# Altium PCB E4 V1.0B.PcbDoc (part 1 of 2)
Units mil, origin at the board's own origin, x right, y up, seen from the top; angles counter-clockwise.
Board outline 3543.31 x 2637.8 mil, 2 copper layers (Top Layer, Bottom Layer), stack 77.559 mil thick; 151 components, 120 nets, 552 pads, 470 vias.
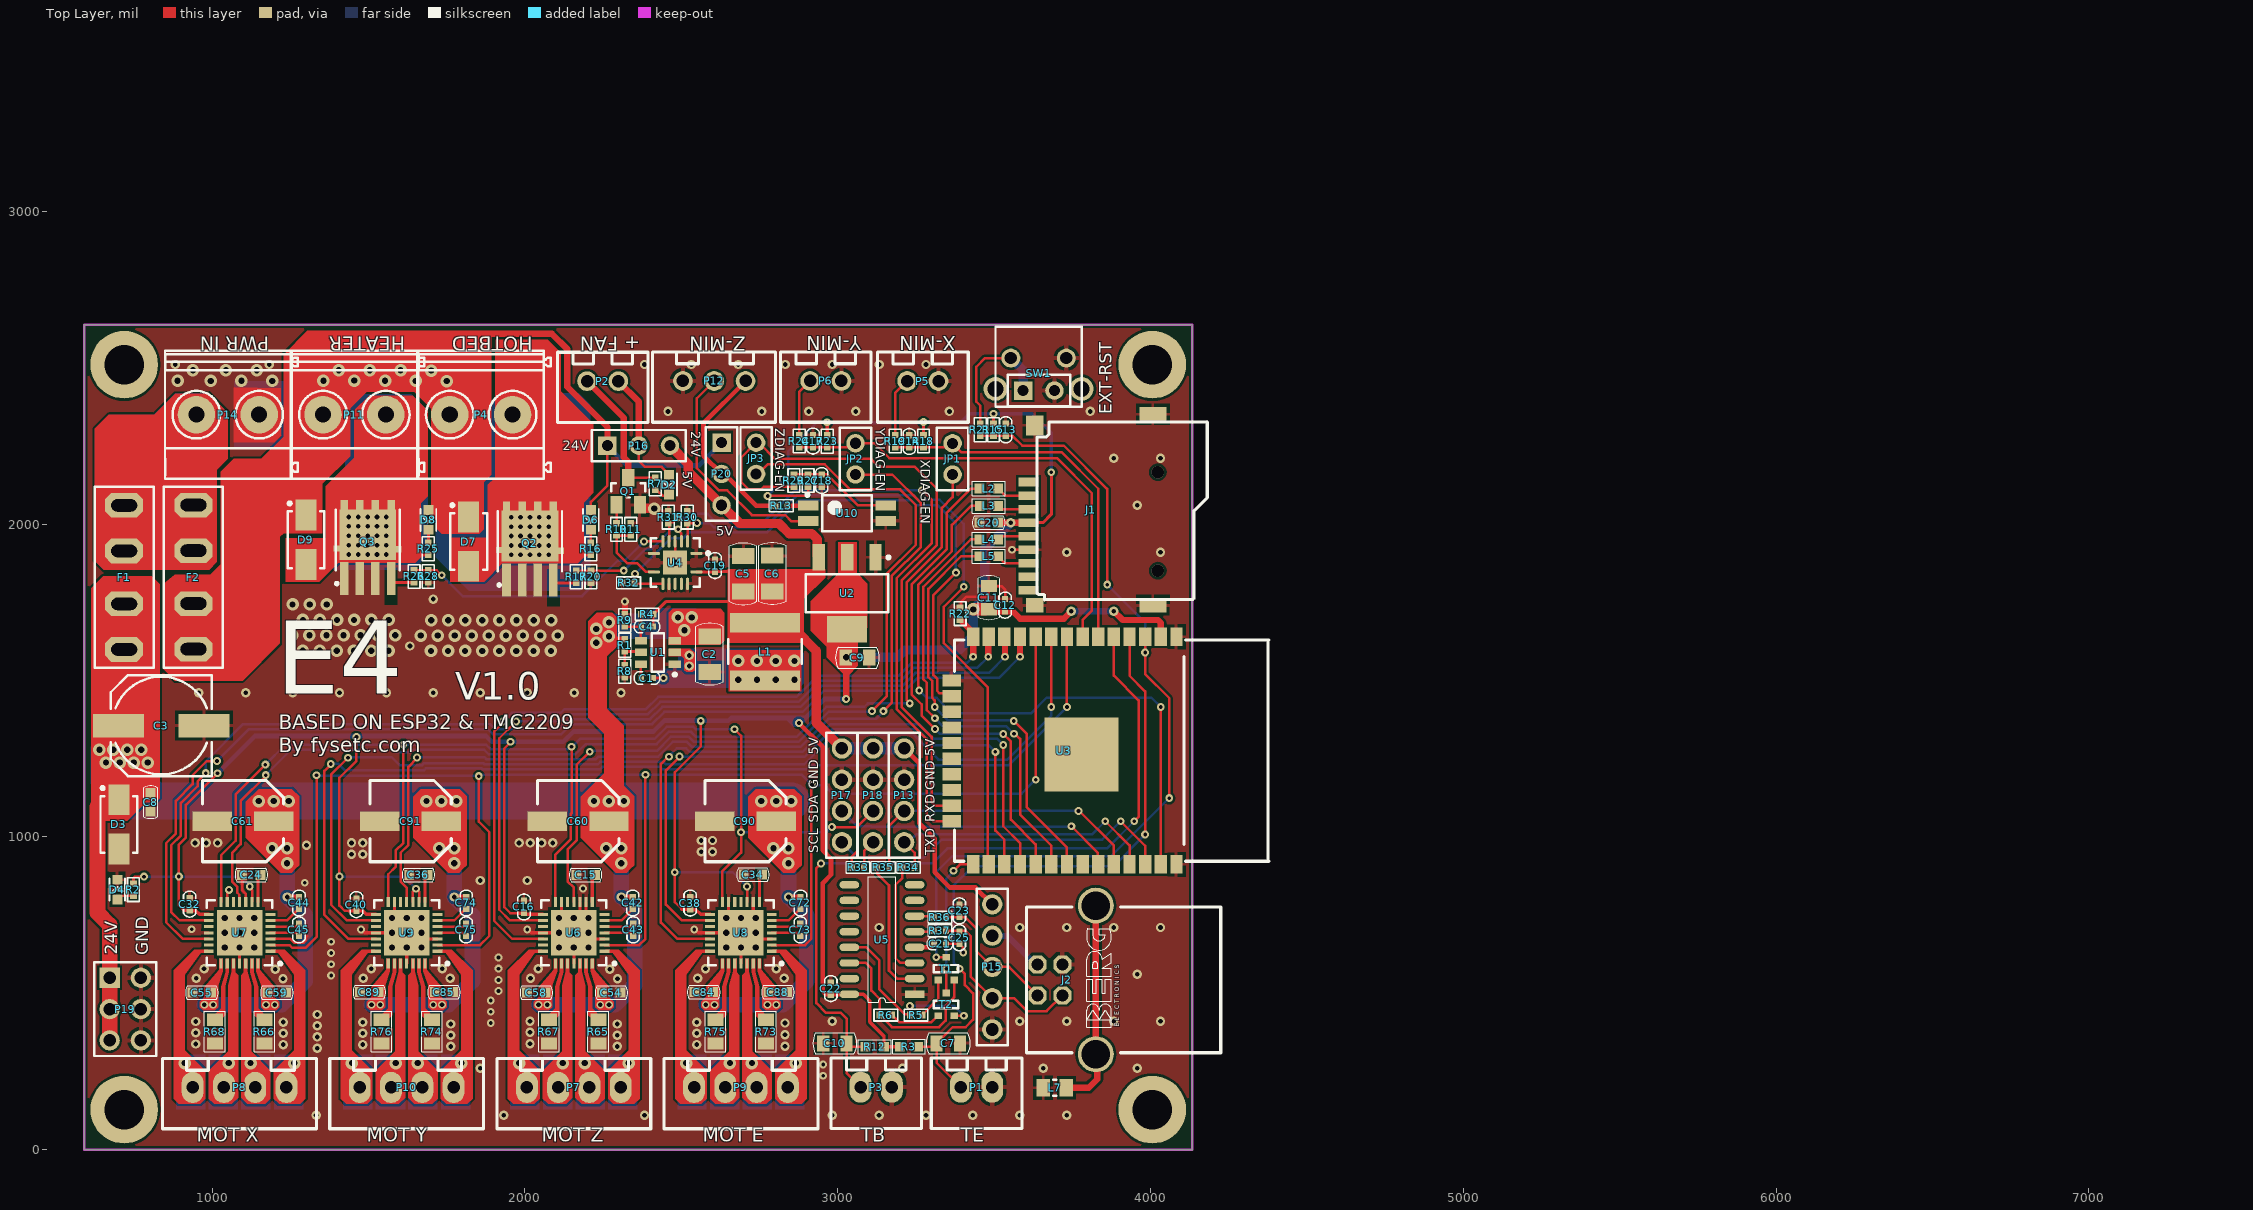
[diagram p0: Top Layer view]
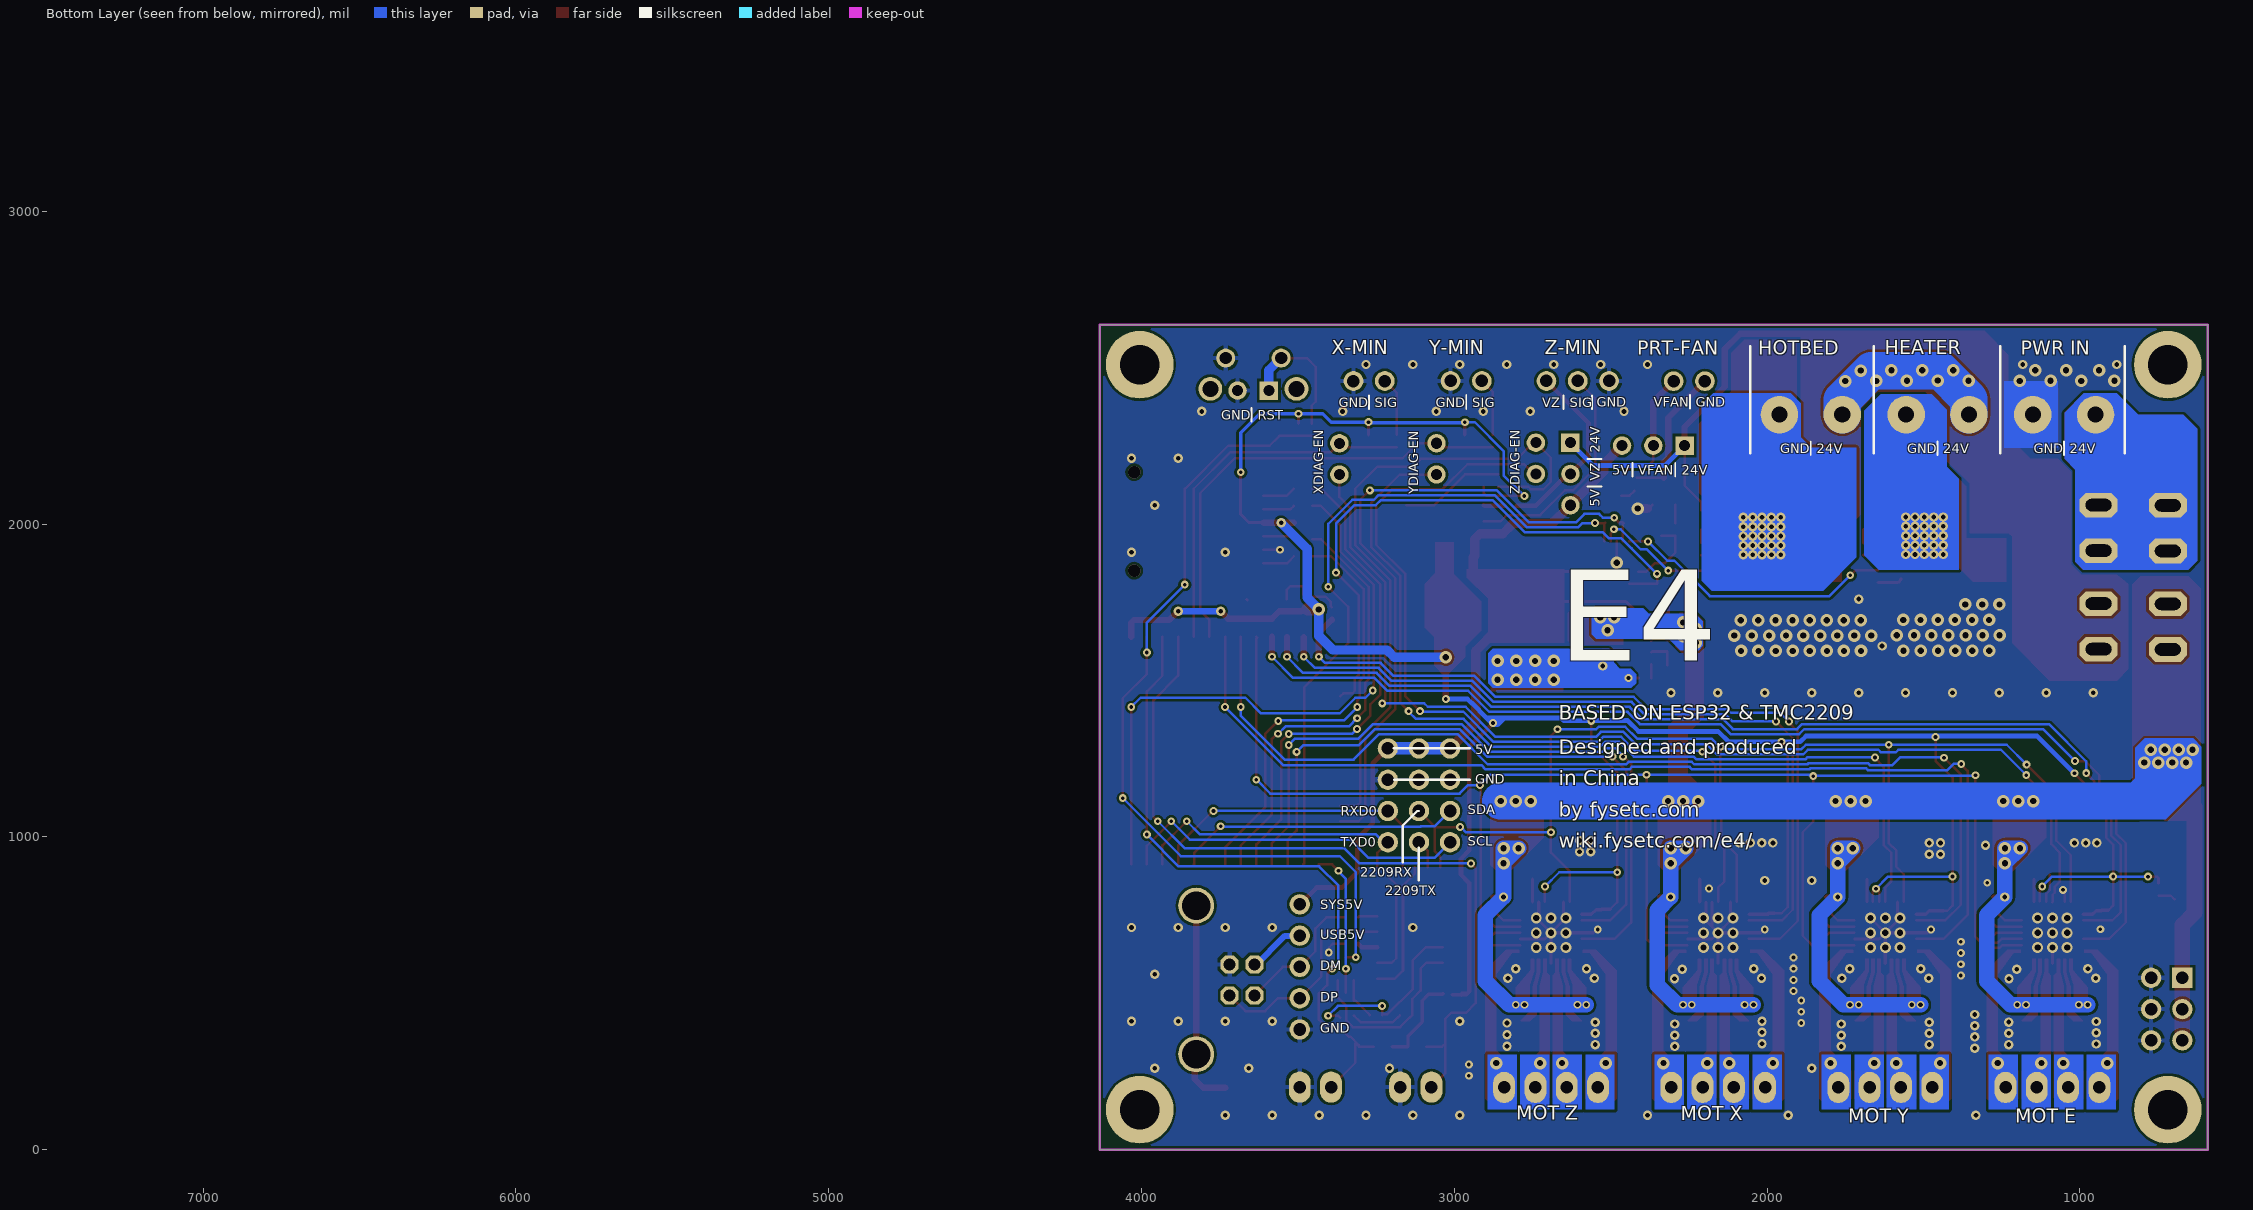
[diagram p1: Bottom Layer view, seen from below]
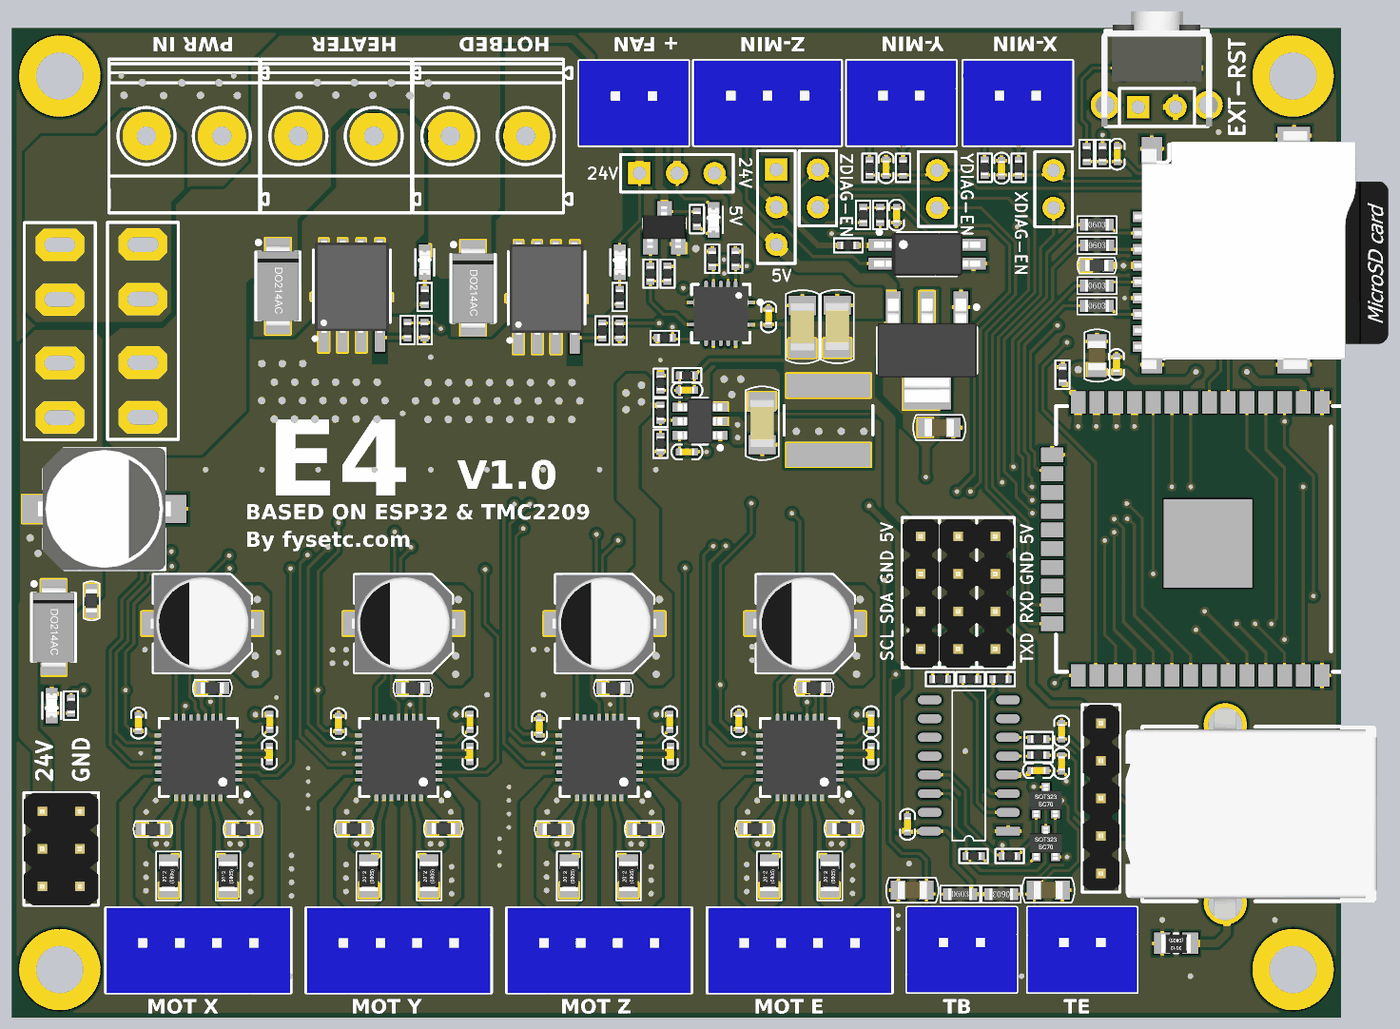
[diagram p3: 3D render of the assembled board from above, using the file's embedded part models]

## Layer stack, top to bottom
Top Solder: solder mask 0.4, Solder Resist, Dk 3.5
Top Layer: signal copper 1.378
Dielectric 1: core 7.874, FR-4, Dk 4.2
Dielectric 2: prepreg 59.0551, Dk 4.2
Dielectric 3: core 7.874, Dk 4.2
Bottom Layer: signal copper 1.378
Bottom Solder: solder mask 0.4, Solder Resist, Dk 3.5

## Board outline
590.55,0 590.55,2637.8 4133.86,2637.8 4133.86,0

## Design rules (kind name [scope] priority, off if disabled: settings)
Clearance Clearance_1 [(InDifferentialPairClass('All Differential Pairs'))] p1: gap=6 ignorepadtopadclearanceinfootprint=TRUE
Clearance [All] p2: gap=8 ignorepadtopadclearanceinfootprint=TRUE
DiffPairsRouting DiffPairsRouting_90R [InDifferentialPairClass('USB')] p1: maxlimit=6 minlimit=6 mostfreqgap=6 toplayer_minwidth=9 toplayer_maxwidth=9 toplayer_prefwidth=9 bottomlayer_minwidth=9 bottomlayer_maxwidth=9 bottomlayer_prefwidth=9 maxuncoupledlength=500
DiffPairsRouting DiffPairsRouting_100R [InDifferentialPairClass('ETH')] p2: maxlimit=6 minlimit=6 mostfreqgap=6 toplayer_minwidth=6.89 toplayer_maxwidth=6.89 toplayer_prefwidth=6.89 bottomlayer_minwidth=6.89 bottomlayer_maxwidth=6.89 bottomlayer_prefwidth=6.89 maxuncoupledlength=500
PolygonConnect PolygonConnect_8 [All vs (HasFootprint('MCCQ-122') or HasFootprint('黄铜镀锡4.8mm插片'))] p1: connectstyle=Direct reliefconductorwidth=10 reliefentries=4 polygonreliefangle="90 Angle" airgapwidth=10
PolygonConnect PolygonConnect_7 [All vs HasFootprint('KPJX-4S')] p2: connectstyle=Direct reliefconductorwidth=10 reliefentries=4 polygonreliefangle="90 Angle" airgapwidth=10
PolygonConnect PolygonConnect_6 [All vs HasFootprint('AO_DFN5x6')] p3: thpad.connectstyle=Relief thpad.reliefconductorwidth=10 thpad.reliefentries=4 thpad.polygonreliefangle="90 Angle" thpad.airgapwidth=10 smdpad.connectstyle=Direct smdpad.reliefconductorwidth=10 smdpad.reliefentries=4 smdpad.polygonreliefangle="90 Angle" smdpad.airgapwidth=10 via.connectstyle=Direct via.reliefconductorwidth=10 via.reliefentries=4 via.polygonreliefangle="90 Angle" via.airgapwidth=10
PolygonConnect PolygonConnect_5 [All vs HasFootprint('CAP0603')] p4: thpad.connectstyle=Relief thpad.reliefconductorwidth=10 thpad.reliefentries=4 thpad.polygonreliefangle="90 Angle" thpad.airgapwidth=10 smdpad.connectstyle=Direct smdpad.reliefconductorwidth=10 smdpad.reliefentries=4 smdpad.polygonreliefangle="90 Angle" smdpad.airgapwidth=10 via.connectstyle=Direct via.reliefconductorwidth=10 via.reliefentries=4 via.polygonreliefangle="90 Angle" via.airgapwidth=10
PolygonConnect PolygonConnect_4 [All vs HasFootprint('8*10.5')] p5: thpad.connectstyle=Relief thpad.reliefconductorwidth=10 thpad.reliefentries=4 thpad.polygonreliefangle="90 Angle" thpad.airgapwidth=10 smdpad.connectstyle=Direct smdpad.reliefconductorwidth=10 smdpad.reliefentries=4 smdpad.polygonreliefangle="90 Angle" smdpad.airgapwidth=10 via.connectstyle=Direct via.reliefconductorwidth=10 via.reliefentries=4 via.polygonreliefangle="90 Angle" via.airgapwidth=10
PolygonConnect PolygonConnect_3 [All vs HasFootprint('DO214AC (SMA)')] p6: thpad.connectstyle=Relief thpad.reliefconductorwidth=10 thpad.reliefentries=4 thpad.polygonreliefangle="90 Angle" thpad.airgapwidth=10 smdpad.connectstyle=Direct smdpad.reliefconductorwidth=10 smdpad.reliefentries=4 smdpad.polygonreliefangle="90 Angle" smdpad.airgapwidth=10 via.connectstyle=Direct via.reliefconductorwidth=10 via.reliefentries=4 via.polygonreliefangle="90 Angle" via.airgapwidth=10
PolygonConnect PolygonConnect_2 [All vs HasFootprint('RES0805')] p7: thpad.connectstyle=Relief thpad.reliefconductorwidth=10 thpad.reliefentries=4 thpad.polygonreliefangle="90 Angle" thpad.airgapwidth=10 smdpad.connectstyle=Direct smdpad.reliefconductorwidth=10 smdpad.reliefentries=4 smdpad.polygonreliefangle="90 Angle" smdpad.airgapwidth=10 via.connectstyle=Direct via.reliefconductorwidth=10 via.reliefentries=4 via.polygonreliefangle="90 Angle" via.airgapwidth=10
PolygonConnect [All vs HasFootprint('ELCO Case D')] p8: thpad.connectstyle=Relief thpad.reliefconductorwidth=10 thpad.reliefentries=4 thpad.polygonreliefangle="90 Angle" thpad.airgapwidth=10 smdpad.connectstyle=Direct smdpad.reliefconductorwidth=10 smdpad.reliefentries=4 smdpad.polygonreliefangle="90 Angle" smdpad.airgapwidth=10 via.connectstyle=Direct via.reliefconductorwidth=10 via.reliefentries=4 via.polygonreliefangle="90 Angle" via.airgapwidth=10
PolygonConnect PolygonConnect_1 [All] p9: thpad.connectstyle=Relief thpad.reliefconductorwidth=15 thpad.reliefentries=4 thpad.polygonreliefangle="90 Angle" thpad.airgapwidth=10 smdpad.connectstyle=Relief smdpad.reliefconductorwidth=10 smdpad.reliefentries=4 smdpad.polygonreliefangle="90 Angle" smdpad.airgapwidth=10 via.connectstyle=Direct via.reliefconductorwidth=10 via.reliefentries=4 via.polygonreliefangle="90 Angle" via.airgapwidth=10
RoutingVias [All] p1: holewidth=28 width=50 viastyle="Through Hole" minholewidth=12 minwidth=25 maxholewidth=28 maxwidth=50
SolderMaskExpansion [All] p1: expansion=4 istentingtop=FALSE
Width [All] p1: maxlimit=999 minlimit=6 preferedwidth=8
29 further rules are at their usual default settings.

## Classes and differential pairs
component class "U_Trinamic driver": C15 C16 C24 C32 C34 C36 C38 C40 C42 C43 C44 C45 C54 C55 C58 C59 C60 C61 C72 C73 C74 C75 C84 C85 C88 C89 C90 C91 P7 P8 P9 P10 R65 R66 R67 R68 R73 R74 R75 R76 U6 U7 U8 U9
component class E4_V1.0: C1 C2 C3 C4 C5 C6 C7 C8 C9 C10 C11 C12 C13 C14 C17 C18 C19 C20 C21 C22 C23 C25 D2 D3 D4 D6 D7 D8 D9 EXT-RST F1 F2 J1 J2 JP1 JP2 JP3 L1 L2 L3 L4 L5 L7 P1 P2 P3 P4 P5 P6 P11 P12 P13 P14 P15 P16 P17 P18 P19 P20 Q1 Q2 Q3 R1 R2 R3 R4 R5 R6 R7 R8 R9 R10 R11 R12 R13 R15 R16 R17 R18 R19 R20 R21 R22 R23 R24 R25 R26 R27 R28 R29 R30 R31 R32 R33 R34 R35 R36 R37 SW1 T1 T2 U1 U2 U3 U4 U5 U10

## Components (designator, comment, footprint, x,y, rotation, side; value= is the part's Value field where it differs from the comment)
C1 "0.1uF" CAP0402 2390.26,1507.99 r0 top value=100nF
C2 "10uF/35V" CAP1206 2590.7,1584.26 r90 top
C3 "330uF/35V" CASE_E7 837,1356 r90 top
C4 "100pF" CAP0402 2390.26,1672.27 r180 top value=47pF
C5 "100uF/10V" CAP1206 2697.93,1841.13 r90 top value=47uF
C6 "100uF/10V" CAP1206 2790.93,1842.13 r90 top value=47uF
C7 "10uF" CAP0805 3353.45,339.73 r180 top
C8 "100nF" CAP0603 803,1111 r90 top
C9 "10uF" CAP0805 3063,1572.87 r180 top
C10 "10uF" CAP0805 2990.88,339.73 r0 top
C11 "10uF" CAP0805 3483,1764.77 r90 top
C12 "100nF" CAP0402 3535.19,1740.86 r270 top
C13 "100nF" CAP0402 3537.11,2301.7 r90 top
C14 "100nF" CAP0402 3228.84,2264.33 r90 top
C15 "4.7uF" CAP0603 2193.94,878.59 r180 top value=100nF
C16 "100nF" CAP0402 1996.74,775.94 r270 top
C17 "100nF" CAP0402 2920.81,2265.59 r90 top
C18 "100nF" CAP0402 2948.92,2139.33 r270 top
C19 "100nF" CAP0402 2607.84,1867.65 r270 top
C20 "10uF" CAP0603 3483,2005.11 r180 top
C21 "100nF" CAP0402 3327,658.21 r180 top
C22 "100nF" CAP0402 2978,515.03 r270 top
C23 "47pF" CAP0402 3389,763.43 r270 top
C24 "4.7uF" CAP0603 1125.14,878.59 r180 top value=100nF
C25 "47pF" CAP0402 3389,677.6 r90 top
C32 "100nF" CAP0402 928.08,785.1 r270 top
C34 "4.7uF" CAP0603 2728.98,879.59 r180 top value=100nF
C36 "4.7uF" CAP0603 1659.47,878.59 r180 top value=100nF
C38 "100nF" CAP0402 2528.34,788.57 r270 top
C40 "100nF" CAP0402 1461.07,783.57 r270 top
C42 "100nF" CAP0402 2344.5,788.65 r270 top
C43 "22nF" CAP0402 2346.06,702.94 r270 top value=100nF
C44 "100nF" CAP0402 1277.83,788.65 r270 top
C45 "22nF" CAP0402 1277.4,702.94 r270 top value=100nF
C54 "100nF" CAP0603 2276.4,502.28 r180 top
C55 "100nF" CAP0603 966.88,502.29 r0 top
C58 "100nF" CAP0603 2036.41,502.28 r0 top
C59 "100nF" CAP0603 1206.81,502.29 r180 top
C60 "100uF/35V" "ELCO Case D" 2170.27,1050.26 r0 top
C61 "100uF/35V" "ELCO Case D" 1098.41,1050.26 r0 top
C72 "100nF" CAP0402 2880.83,788.65 r270 top
C73 "22nF" CAP0402 2880.4,702.94 r270 top value=100nF
C74 "100nF" CAP0402 1812.17,788.65 r270 top
C75 "22nF" CAP0402 1811.73,702.94 r270 top value=100nF
C84 "100nF" CAP0603 2571.7,503.84 r0 top
C85 "100nF" CAP0603 1740.93,503.84 r180 top
C88 "100nF" CAP0603 2808.77,503.84 r180 top
C89 "100nF" CAP0603 1502.34,503.84 r0 top
C90 "100uF/35V" "ELCO Case D" 2705.19,1050.26 r0 top
C91 "100uF/35V" "ELCO Case D" 1634.5,1050.26 r0 top
D2 "LED_0603" LED0603 2460.76,2126.43 r180 top
D3 "SMAJ28A" "DO214AC (SMA)" 702,1040 r90 top
D4 "LED黄色" LED0603 696.8,831.44 r0 top
D6 "LED_0603" LED0603 2211.08,2013.37 r180 top
D7 "SK310A-TP" "DO214AC (SMA)" 1820.08,1944.28 r90 top
D8 "LED_0603" LED0603 1691.25,2013.37 r180 top
D9 "SK310A-TP" "DO214AC (SMA)" 1299.98,1950 r90 top
EXT-RST "Header 2" HDR1X2#1 3593,2427 r0 top
F1 "3A" MCCQ-122 718.5,1914.29 r180 top
F2 "7.5A" MCCQ-122 940,1915.29 r180 top
J1 "TFcard" MicroSD_1 4023.43,2166.06 r90 top
J2 "USB connector" CON-BERG_PN61729-S 3825.21,542.34 r90 top
JP1 "Jumper-2P-Open" HDR1X2#2 3367.4,2158.42 r90 top
JP2 "Jumper-2P-Open" HDR1X2#2 3056.86,2158.67 r90 top
JP3 "Jumper-2P-Open" HDR1X2#2 2739.26,2160.42 r90 top
L1 "22uH" NRS6045 2767.61,1592.25 r90 top
L2 "Bead" RES0603 3483,2113.69 r0 top
L3 "Bead" RES0603 3483.47,2058.51 r0 top
L4 "Bead" RES0603 3483,1951.11 r0 top
L5 "Bead" RES0603 3483,1897.37 r0 top
L7 "Bead" L0805 3694,198 r180 top
P1 "Header 2" XH2.54-2P-L#1 3444,200 r0 top
P2 "Header 2" XH2.54-2P-L#2 2248.68,2457 r0 top
P3 "Header 2" XH2.54-2P-L#1 3123,200 r0 top
P4 "Header 2" KF128/129 1860,2350 r0 top
P5 "Header 2" XH2.54-2P-L#2 3272.32,2457.57 r0 top
P6 "Header 2" XH2.54-2P-L#2 2961.86,2457.83 r0 top
P7 "Header 4" XH2.54-4P-L 2156.27,198.89 r0 top
P8 "Header 4" XH2.54-4P-L 1087.61,198.89 r0 top
P9 "Header 4" XH2.54-4P-L 2690.61,198.89 r0 top
P10 "Header 4" XH2.54-4P-L 1621.94,198.89 r0 top
P11 "Header 2" KF128/129 1454.84,2350 r0 top
P12 "Header 3" XH2.54-3P-L 2605.26,2457.65 r0 top
P13 "Header 4" "Header 1X4" 3212.38,982.85 r90 top
P14 "Header 2" KF128/129 1050,2350 r0 top
P15 "Header 5" "Header 1X5" 3494,784.26 r270 top
P16 "Header 3" HDR1X3 2263.68,2251 r0 top
P17 "Header 4" "Header 1X4" 3013.62,982.85 r90 top
P18 "Header 4" "Header 1X4" 3113,982.85 r90 top
P19 "Header 3X2" "Header 2X3" 672.02,549.44 r270 top
P20 "Header 3" HDR1X3 2628.7,2260.42 r270 top
Q1 "MMBF170" SOT23-3 2330.22,2105.16 r180 top
Q2 "WSD40150" AO_DFN5x6 2016.09,1943.08 r0 top value=IRF8736PBF
Q3 "WSD4060" AO_DFN5x6 1496.98,1947.76 r0 top value=IRF8736PBF
R1 "500K" RES0402 2319.5,1612.45 r90 top
R2 "620R" RES0402 748.26,831.44 r270 top value=49.9k
R3 "4.7K" RES0603 3227.9,329.26 r180 top
R4 "100K" RES0402 2390.33,1712.15 r180 top value=49.9k
R5 "10K" RES0402 3250.42,430.39 r0 top
R6 "10K" RES0402 3154.11,430.39 r180 top
R7 "2.2K" RES0402 2416.69,2128.78 r270 top
R8 "100K" RES0402 2319.5,1529.58 r90 top
R9 "13.3K" RES0402 2319.5,1691.96 r90 top value=9.53k
R10 "100R" RES0402 2292.82,1983.17 r270 top
R11 "100K" RES0402 2338.18,1983.17 r90 top
R12 "4.7K" RES0603 3118.57,329.26 r0 top
R13 "1K" RES0402 2820,2058.51 r180 top
R15 "10K" RES0402 3498.11,2302.05 r90 top
R16 "10K" RES0402 2210.93,1920.96 r90 top
R17 "100R" RES0402 2164.5,1831.67 r90 top
R18 "10K" RES0402 3274.26,2265.71 r270 top
R19 "100R" RES0402 3183.81,2265.71 r270 top
R20 "100K" RES0402 2210.98,1831.65 r270 top
R21 "1K" RES0402 3455.75,2302.05 r270 top
R22 "10K" RES0402 3391.21,1713.84 r270 top
R23 "10K" RES0402 2966.23,2265.29 r270 top
R24 "100R" RES0402 2876.73,2265.59 r270 top
R25 "10K" RES0402 1691.25,1920.96 r90 top
R26 "100R" RES0402 1645.39,1832.65 r90 top
R27 "10K" RES0402 2905.11,2139.45 r90 top
R28 "100K" RES0402 1690.79,1832.65 r270 top
R29 "100R" RES0402 2860.1,2139.33 r270 top
R30 "1.8K" RES0402 2519.33,2022.53 r90 top
R31 "1.8K" RES0402 2457.74,2022.53 r90 top
R32 "1.8K" RES0402 2331.4,1812.05 r180 top
R33 "10K" RES0402 3065,902.16 r180 top
R34 "1K" RES0402 3226.26,902.16 r0 top
R35 "1K" RES0402 3145.65,902.16 r0 top
R36 "22R" RES0402 3327,742.56 r180 top
R37 "22R" RES0402 3327,699.56 r180 top
R65 "0.22R" RES0805 2234.4,377.44 r90 top
R66 "0.22R" RES0805 1166.74,377.44 r90 top
R67 "0.22R" RES0805 2076.41,377.44 r90 top
R68 "0.22R" RES0805 1008.36,377.44 r90 top
R73 "0.22R" RES0805 2771.07,377.44 r90 top
R74 "0.22R" RES0805 1702.57,377.44 r90 top
R75 "0.22R" RES0805 2609.76,377.44 r90 top
R76 "0.22R" RES0805 1541.73,377.44 r90 top
SW1 "Momentary Tactile Button" "7.5x6x6.5 侧按开关" 3553.75,2531 r0 top
T1 "S9014" SOT323_3_SC70 3346.68,578.64 r180 top
T2 "S9014" SOT323_3_SC70 3346.68,464.6 r180 top
U1 "TPS54202" SOT23-6N 2424.93,1589.76 r180 top
U2 "AMS1117-3.3" SOT-223 3030.27,1778.63 r270 top
U3 "ESP-WROOM-32" WIFIM-SMD_ESP-WROOM-32 3723.5,1276 r270 top locked
U4 "AHCT125" QFN14 2480.43,1876.91 r180 top
U5 "CH340C" SOP16 3245.94,496.89 r180 top
U6 "TMC2209" "QFN28 (2209)" 2156.27,693.36 r180 top locked
U7 "TMC2209" "QFN28 (2209)" 1087.61,693.36 r180 top locked
U8 "TMC2209" "QFN28 (2209)" 2690.61,693.36 r180 top locked
U9 "TMC2209" "QFN28 (2209)" 1621.94,693.36 r180 top locked
U10 "JC3H7/TLP291" SOIC127P720X210-4N 3030,2035 r0 top

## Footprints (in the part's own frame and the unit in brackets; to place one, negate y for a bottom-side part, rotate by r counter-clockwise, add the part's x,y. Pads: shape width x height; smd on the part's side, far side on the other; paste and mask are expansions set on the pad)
"7.5x6x6.5 侧按开关" [mm]
  round 1.54 hole 1: 1(0,0) 2(4.5,0)
  round 1.93 hole 1.3: 3(-1.25,-2.5) 4(5.75,-2.5)
  silkscreen extent -1.25,-3.95 5.75,2.55, body extent -1.84,-3.95 6.34,3.85, height 7.1
AO_DFN5x6 [mm] "Alpha & Omega DFN 5x6 mm"
  rect 0.7x2.667 smd: 1(-1.905,-3.079) 2(-0.635,-3.079) 3(0.635,-3.079) 4(1.905,-3.079)
  rect 0.6x0.75 smd: 5(1.905,2.895) 6(0.635,2.895) 7(-0.635,2.895) 8(-1.905,2.895)
  rect 0.55x0.5 smd: 8(-2.488,-0.66) 8(2.488,-0.711)
  rect 4.6x4.12 smd: 8(0,0.475)
  silkscreen extent -2.6,-3.6 2.6,2.5, body extent -2.62,-3.12 2.63,3.12, height 1.14
CAP0402 [mm]
  rect 0.5x0.5 smd: 1(-0.5,0) 2(0.5,0)
  silkscreen extent -1.05,-0.5 1.05,0.5, body extent -0.5,-0.25 0.5,0.25, height 0.5
CAP0603 [mm]
  rect 0.8x0.8 smd mask+0.1: 1(-0.75,0) 2(0.75,0)
  silkscreen extent -1.32,-0.55 1.32,0.55, body extent -0.8,-0.4 0.8,0.4, height 0.9
CAP0805 [mm]
  rect 1x1.3 smd: 1(-0.95,0) 2(0.95,0)
  silkscreen extent -1.78,-0.85 1.78,0.85, body extent -1,-0.6 1,0.6, height 1.2
CAP1206 [mm]
  rect 1.3x1.85 smd: 1(-1.45,0) 2(1.45,0)
  silkscreen extent -2.5,-1.12 2.5,1.12, body extent -1.6,-0.8 1.6,0.8, height 0.77
CASE_E7 [mm] "SMD Polymer Capacitor, 8.3x8.3mm, Diameter 8mm"
  rect 1.9x4.15 smd: 1(0,3.475) 2(0,-3.475)
  silkscreen extent -4.1,-4.1 4.1,4.1, body extent -4.15,-4.5 4.15,4.5, height 6.9
CON-BERG_PN61729-S [mil]
  oct 57x57 hole 38: 1(50,186) 2(-49.21,186) 3(-49.21,107) 4(50,107)
  round 115 hole 91: S1(-237.01,0) S2(238,0)
  silkscreen extent -232,-400 233,221, body extent -292,-404 294,265, height 433
"DO214AC (SMA)" [mm]
  rect 2.5x1.7 smd: 1(-2,0) 2(2,0)
  silkscreen extent -2.3,-1.5 3.07,1.5, body extent -2.74,-1.4 2.74,1.4, height 2.3
"ELCO Case D" [mm]
  rect 3.2x1.6 smd: 1(2.5,0) 2(-2.5,0)
  silkscreen extent -3.3,-3.3 3.3,3.3, body extent -3.5,-3.3 3.5,3.3, height 5.41
HDR1X2#1 [mm] "Connector; Header; 2 Position"
  rect 1.5x1.5 hole 0.9: 1(0,0)
  round 1.5 hole 0.9: 2(2.54,0)
  silkscreen extent -1.27,-1.27 3.81,1.27
HDR1X2#2 [mm] "Connector; Header; 2 Position"
  round 1.5 hole 0.9: 1(0,0) 2(2.54,0)
  silkscreen extent -1.27,-1.27 3.81,1.27
HDR1X3 [mm] "Connector; Header; 3 Position"
  rect 1.5x1.5 hole 0.9: 1(0,0)
  round 1.5 hole 0.9: 2(2.54,0) 3(5.08,0)
  silkscreen extent -1.27,-1.27 6.35,1.27
"Header 1X4" [mm]
  round 1.65 hole 1.02: 1(0,0) 2(2.54,0) 3(5.08,0) 4(7.62,0)
  silkscreen extent -1.27,-1.27 8.89,1.27, body extent -1.27,-1.25 8.79,1.25, height 8.3
"Header 1X5" [mm]
  round 1.65 hole 1.02: 1(0,0) 2(2.54,0) 3(5.08,0) 4(7.62,0) 5(10.16,0)
  silkscreen extent -1.27,-1.27 11.43,1.27, body extent -1.27,-1.25 11.33,1.25, height 8.3
"Header 2X3" [mm]
  rect 1.65x1.65 hole 1.02: 1(0,0)
  round 1.65 hole 1.02: 2(0,2.54) 3(2.54,0) 4(2.54,2.54) 5(5.08,0) 6(5.08,2.54)
  silkscreen extent -1.27,-1.25 6.35,3.79, body extent -1.27,-1.27 6.35,3.81, height 8.5
KF128/129 [mil]
  round 120 hole 51.18: 1(-100.42,0) 2(100.42,0)
  silkscreen extent -201,-205 223,205, body extent -197,-209 440,208, height 720
L0805 [mm]
  rect 1.1x1.45 smd: 1(-0.95,0) 2(0.95,0)
  silkscreen extent -0.13,-0.64 0.13,0.64, body extent -1,-0.6 1,0.65, height 0.44
LED0603 [mm]
  rect 0.8x0.8 smd: 1(0,0.8) 2(0,-0.8)
  silkscreen extent -0.64,-0.89 0.64,0.89, body extent -0.37,-0.81 0.36,0.84, height 0.68
MCCQ-122 [mm]
  oct 3.1x2 hole 1 slot 2.1 at 0 deg: 1(0,0) 1(0,-3.7) 2(0,8) 2(0,4.3)
  silkscreen extent -2.4,-5.2 2.4,9.5
MicroSD_1 [mm]
  rect 0.7x1.6 smd: 1(-0.8,10.5) 2(-1.9,10.5) 3(-3,10.5) 4(-4.1,10.5) 5(-5.2,10.5) 6(-6.3,10.5) 7(-7.4,10.5) 8(-8.5,10.5) 9(-9.6,10.5)
  rect 1.2x1.4 smd: 10(-10.8,10)
  rect 1.2x2.2 smd: 11(-10.8,0.4) 12(4.7,0.4)
  rect 1.6x1.4 smd: 13(3.8,10)
  Top Layer lines w0.254: -10.394,9.188 -10.343,9.138
  silkscreen extent -10.39,-4.02 4.1,9.8, body extent -11.1,-6 5,11.2, height 2.2
NRS6045 [mm]
  rect 1.6x5.7 smd: 1(-2.35,0) 2(2.35,0)
  silkscreen extent -1,-3 1,3, body extent -3,-3 3,3, height 4.5
QFN14 [mm]
  oval 1x0.25 smd: 1(-1.725,-0.75) 7(1.725,-0.75) 8(1.725,0.75) 14(-1.725,0.75)
  oval 0.25x1 smd: 2(-1,-1.725) 3(-0.5,-1.725) 4(0,-1.725) 5(0.5,-1.725) 6(1,-1.725) 9(1,1.725) 10(0.5,1.725) 11(0,1.725) 12(-0.5,1.725) 13(-1,1.725)
  rect 1.95x1.95 smd: 15(0,0)
  silkscreen extent -2.79,-1.97 1.97,1.97, body extent -1.84,-1.84 1.84,1.84, height 0.8
"QFN28 (2209)" [mm]
  rect 0.8x0.25 smd mask+0.051: 1(-2.503,1.5) 2(-2.503,1) 3(-2.503,0.5) 4(-2.503,0) 5(-2.503,-0.5) 6(-2.503,-1) 7(-2.503,-1.5) 15(2.503,-1.5) 16(2.503,-1) 17(2.503,-0.5) 18(2.503,0) 19(2.503,0.5) 20(2.503,1) 21(2.503,1.5)
  rect 0.25x0.8 smd mask+0.051: 8(-1.5,-2.503) 9(-1,-2.503) 10(-0.5,-2.503) 11(0,-2.503) 12(0.5,-2.503) 13(1,-2.503) 14(1.5,-2.503) 22(1.5,2.503) 23(1,2.503) 24(0.5,2.503) 25(0,2.503) 26(-0.5,2.503) 27(-1,2.503) 28(-1.5,2.503)
  rect 3.7x3.7 smd mask+0.051: EXPAD(0,0)
  silkscreen extent -3.42,-2.65 2.65,2.65, body extent -2.52,-2.52 2.52,2.52, height 0.85
RES0402 [mm]
  rect 0.5x0.54 smd: 1(-0.5,0) 2(0.5,0)
  silkscreen extent -0.97,-0.48 0.97,0.48, body extent -0.5,-0.25 0.5,0.25, height 0.5
RES0603 [mm]
  rect 0.8x0.8 smd mask+0.1: 1(-0.75,0) 2(0.75,0)
  silkscreen extent -1.33,-0.58 1.33,0.58, body extent -0.8,-0.4 0.8,0.4, height 0.45
RES0805 [mm]
  rect 1x1.3 smd: 1(-0.958,0) 2(0.958,0)
  silkscreen extent -1.65,-0.84 1.65,0.84, body extent -1.03,-0.62 0.97,0.63, height 0.44
SOIC127P720X210-4N [mm] "SOIC, 4-Leads, Body 2.65x4.60mm, Pitch 1.27mm, IPC Medium Density"
  rect 1.65x0.8 smd: 1(-3.15,0.635) 2(-3.15,-0.635) 3(3.15,-0.635) 4(3.15,0.635)
  silkscreen extent -3.35,-1.45 2,1.61, body extent -3.6,-1.45 3.6,1.45, height 2.1
SOP16 [mm]
  rect 1.6x0.6 smd: 1(0,0)
  oval 1.6x0.6 smd: 2(0,-1.27) 3(0,-2.54) 4(0,-3.81) 5(0,-5.08) 6(0,-6.35) 7(0,-7.62) 8(0,-8.89) 9(5.3,-8.89) 10(5.3,-7.62) 11(5.3,-6.35) 12(5.3,-5.08) 13(5.3,-3.81) 14(5.3,-2.54) 15(5.3,-1.27) 16(5.3,0)
  silkscreen extent 1.53,-9.53 3.77,0.64
SOT23-3 [mm] "SOT23, 3-Leads, Body 2.9x1.3mm, Pitch 0.95mm, Lead Span 2.5mm, IPC High Density"
  rect 1x1.4 smd: 1(0.95,1.1) 2(-0.95,1.1) 3(0,-1.1)
  silkscreen extent -1.4,-0.64 1.4,0.51, body extent -1.44,-1.45 1.46,1.35, height 1.07
SOT23-6N [mm]
  rect 1x0.6 smd: 1(-1.375,0.95) 2(-1.375,0) 3(-1.375,-0.95) 4(1.375,-0.95) 5(1.375,0) 6(1.375,0.95)
  silkscreen extent -1.5,-1.55 0.5,1.92, body extent -1.5,-1.52 1.5,1.52, height 1.45
SOT323_3_SC70 [mm] "SOT 323-3 SC-70, Reflow footprint"
  rect 0.6x0.55 smd: 1(0.65,0.925) 2(-0.65,0.925) 3(0,-0.925)
  silkscreen extent -1,-0.3 1,0.3, body extent -1.1,-1.12 1.1,1.12, height 1.1
SOT-223 [mm] "SOT223, 4-Leads, Body 6.50x7.00mm (avg), Pitch 2.30mm, IPC Medium Density"
  rect 2.15x1 smd: 1(-2.925,2.3) 2(-2.925,0) 3(-2.925,-2.3)
  rect 2.15x3.25 smd: 4(2.925,0)
  silkscreen extent -3.05,-3.35 1.55,3.48, body extent -3.5,-3.35 3.5,3.35, height 1.8
WIFIM-SMD_ESP-WROOM-32 [mil]
  rect 59.1x39.4 smd: 1(-364,359.5) 2(-364,309.5) 3(-364,259.5) 4(-364,209.5) 5(-364,159.5) 6(-364,109.5) 7(-364,59.5) 8(-364,9.5) 9(-364,-40.5) 10(-364,-90.5) 11(-364,-140.5) 12(-364,-190.5) 13(-364,-240.5) 14(-364,-290.5) 25(364,-290.5) 26(364,-240.5) 27(364,-190.5) 28(364,-140.5) 29(364,-90.5) 30(364,-40.5) 31(364,9.5) 32(364,59.5) 33(364,109.5) 34(364,159.5) 35(364,209.5) 36(364,259.5) 37(364,309.5) 38(364,359.5)
  rect 39.4x59.1 smd: 15(-224,-359.5) 16(-174,-359.5) 17(-124,-359.5) 18(-74,-359.5) 19(-24,-359.5) 20(26,-359.5) 21(76,-359.5) 22(126,-359.5) 23(176,-359.5) 24(226,-359.5)
  rect 236.2x236.2 smd: 39(12,55.5)
  silkscreen extent -354,-349 354,654
XH2.54-2P-L#1 [mil]
  oval 70x100 hole 40: 1(-50,0) 2(50,0)
  silkscreen extent -145,-132 145,93, body extent -146,-133 146,93, height 276
XH2.54-2P-L#2 [mil]
  round 62.99 hole 40: 1(-50,0) 2(50,0)
  silkscreen extent -145,-132 145,93, body extent -146,-133 146,93, height 276
XH2.54-3P-L [mm]
  round 1.6 hole 1.016: 1(2.54,0) 2(0,0) 3(-2.54,0)
  silkscreen extent -5,-3.35 4.98,2.35, body extent -4.95,-3.38 4.95,2.38, height 7
XH2.54-4P-L [mil]
  oval 70x100 hole 40: 1(150,0) 2(50,0) 3(-50,0) 4(-150,0)
  silkscreen extent -246,-132 246,93, body extent -244,-133 244,94, height 276

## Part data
C1 C4 C5 C6 C14 C15 C16 C17 C18 C19 C24 C32 C34 C36 C38 C40 C43 C45 C73 C75: library part Library_CAP-0008, "RO C0G 22pF 2% 50V  0603"
C2 C7 C8 C9 C10 C11 C12 C13 C20 C42 C44 C54 C55 C58 C59 C72 C74 C84 C85 C88 C89: library part Capacitor
C3: library part Library_CAP-0004, "RO ELCO 100uF 20% 35V CASE-D EEEFP PAN"
C21 C22: library part Library_CAP-0006, "RO X5R 1uF 10% 10V 0603"
C23 C25: library part Library_CAP-0002, "RO X7R 100nF 10% 50V 0603"
C60 C61 C90 C91: "RO ELCO 100uF 20% 35V CASE-D EEEFP PAN"
D3 D7 D9: library part Diode, "Default Diode"
D4: library part LED_0603
EXT-RST P1 P2 P3 P4 P5 P6 P11 P14: "Header, 2-Pin"
F1 F2: library part "Fuse 2", "Fuse"
J2: library part CON-BERG_PN61729-S
L1: library part Inductor, "Inductor"
L2 L3 L4 L5: "RO FERRIET BLM21PG221SN1D  0805"
L7: library part Library_COIL-0001, "RO FERRIET BLM21PG221SN1D  0805"
P7 P8 P9 P10 P13 P17 P18: "Header, 4-Pin"
P12 P16 P20: "Header, 3-Pin"
P15: "Header, 5-Pin"
P19: "Header, 3-Pin, Dual row"
Q1: library part N-MOS
Q2 Q3: "IRF8736PBF - MOSFET, N SO-8"
R1 R3 R7 R8 R10 R11 R12 R13 R15 R16 R17 R18 R19 R20 R21 R22 R23 R24 R25 R26 R27 R28 R29 R30 R31 R32 R33 R65 R66 R67 R68 R73 R74 R75 R76: library part Resistor
R2 R4 R9: library part Library_RES-0001, "RO RES 10k0 1% 0,063W  0603"
R5 R6 R34 R35 R36 R37: library part Library_RES-0007, "RO RES 22E0 1% 0,063W 0603"
SW1: library part SW-PB, "SWITCH TACTILE SPST-NO 0.05A 12V", Supplier Part Number 1=679-2396-1-ND
T1 T2: "RO TRANS BC817-25  SOT-23"
U2: library part 1117
U3: BOM_Manufacturer=ESPRESSIF
U4: library part 74HC125
U5: library part CH340G
U10: library part Optoisolator1, "4-Pin Phototransistor Optocoupler"

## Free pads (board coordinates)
  round 216.54 hole 125.98: 4(718.5,2509.84) 4(718.5,127.95) 4(4005.91,127.95) 4(4005.91,2509.84)

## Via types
v1: diameter 30, hole 15, Top Layer to Bottom Layer, tented both sides, 177 vias
v2: diameter 40, hole 20, Top Layer to Bottom Layer, tented both sides, 114 vias
v3: diameter 25, hole 12, Top Layer to Bottom Layer, tented both sides, 109 vias
v4: diameter 35, hole 20, Top Layer to Bottom Layer, 36 vias
v5: diameter 40, hole 20, Top Layer to Bottom Layer, 16 vias
v6: diameter 25, hole 15, Top Layer to Bottom Layer, tented both sides, 16 vias
v7: diameter 39.37, hole 39.37, Top Layer to Bottom Layer, 2 vias

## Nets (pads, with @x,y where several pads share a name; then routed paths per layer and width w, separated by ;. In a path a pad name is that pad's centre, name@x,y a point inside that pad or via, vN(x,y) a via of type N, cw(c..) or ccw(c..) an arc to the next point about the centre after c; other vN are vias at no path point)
24V2: D6.2 D7.2 D8.2 D9.2 F2.2 P4.1 P11.1 P16.1 P20.1 | length 1963.9
  Top Layer w8: D6.2@2211.08,2044.87 2211.08,2071 2263.68,2123.6 P16.1@2263.68,2251
  Top Layer w20: 1781.02,2608.7 2086.3,2608.7 2135,2560 2135,2439.61 2263.68,2310.93 P16.1@2263.68,2251
  Bottom Layer w15: P16.1@2263.68,2251 2327.5,2187.18 2555.46,2187.18 P20.1@2628.7,2260.42
  Bottom Layer w120: P11.1@1354.43,2350 1354.43,2399.43 1445,2490 1666.72,2490 1759.58,2397.14 P4.1@1759.58,2350
  other v2: 1749.63,2457.31 1355.92,2458.57 1552.78,2458.57 1651.2,2457.94 1454.35,2459.2 1602.2,2491.65 1700.63,2491.02 1404.92,2492.28 1503.78,2492.28
340_RX: R34.1 U5.3 | length 365.6
  Top Layer w8: R34.1@3206.57,902.16 3206.57,868.41 3185.51,847.35 3185.51,611.94 3200.57,596.89 U5.3@3245.94,596.89
340_TX: R35.1 U5.2 | length 437.8
  Top Layer w8: R35.1@3125.97,902.16 3125.97,883.16 3164,845.13 3164,572.78 3189.9,546.89 U5.2@3245.94,546.89
+3.3V: C9.2 C11.1 C12.2 C16.2 C20.1 C22.2 C32.2 C38.2 C40.2 J1.4 R2.1 R3.2 R12.2 R15.2 R18.1 R23.1 R27.1 U2.2 U2.4 U3.2 U5.16 U6.15 U7.9 U7.15 U8.10 U8.15 U9.9 U9.10 U9.15 | length 10721.3
  Top Layer w8: 748.37,868.54 748.26,868.43 R2.1@748.26,851.13 748.62,851.49 748.62,868.28 753.31,872.96 v3(782.25,872.96) ; 908.39,765.41 893.5,780.3 v3(893.5,873) 893.5,975.06 916,997.56 916,1102 v3(1017.24,1203.24) ; v3(1120.41,841.68) 1120.41,837.08 1127.41,830.08 U7.9@1127.41,794.68 ; 1437.07,763.89 1423.69,763.89 1407,780.58 v3(1407,873) 1407,1189 1461.07,1243.07 v3@1461.07,1314.02 ; U9.10@1641.63,791.89 1641.63,823.94 v3(1651.82,834.13) ; U9.9@1661.31,791.89 1661.31,823.94 ; v3@1954.59,1302.88 1933.97,1282.25 1933.97,775.28 1952.99,756.25 1977.05,756.25 ; 2501.57,768.68 2479.07,791.19 v3(2479.07,886.83) 2479.07,1206.42 2562,1289.35 v3(2562,1371) ; U8.10@2710.29,791.89 v3@2710.29,837.94 ; v3(2776.04,2089.95) 2897.17,2089.95 2905.11,2097.88 R27.1@2905.11,2119.76 ; C11.1@3470.61,1727.37 3476.81,1721.17 C11.1@3483,1727.37 C11.1@3489.19,1721.17
  Top Layer w10: J1.4@3610.05,2004.64 3656.51,2004.64 3683,2031.13 v3(3683,2166.06)
  Top Layer w11: 908.39,765.41 C32.2@928.08,765.41 ; C32.2@930.41,765.68 932.02,764.07 947.75,764.07 959.41,752.41 U7.15@989.07,752.41 ; 1437.07,763.89 C40.2@1461.07,763.89 1481.43,763.89 1492.91,752.41 U9.15@1523.41,752.41 ; 1977.05,756.25 C16.2@1996.74,756.25 ; C16.2@1996.74,752.41 U6.15@2057.74,752.41 ; 2501.57,768.89 C38.2@2528.34,768.89 2529.72,767.51 2546.47,767.51 2561.57,752.41 U8.15@2592.07,752.41 ; R23.1@2966.23,2284.98 v3(2966.23,2325.62) ; C22.2@2978,495.34 3006.22,495.34 U5.16@3006.25,495.3 ; U5.16@3034.87,499.3 U5.16@3037.28,496.89 3082.37,496.89 3103,476.26 3103,408.3 3148.1,363.2 R12.2@3148.1,329.26 R3.2@3198.37,329.26 ; R18.1@3274.26,2285.39 v3(3274.26,2326.04) ; R15.2@3498.11,2321.74 v3(3498.11,2353.07) ; C20.1@3512.53,2005.11 C20.1@3513,2004.64
  Top Layer w15: v3(2875.88,1364.2) 2951.83,1288.24 2951.83,957.19 2978.52,930.5 2978.52,879.21 2951.83,852.52 2951.83,506.47 2960.62,497.68 2975.66,497.68 C22.2@2978,495.34
  Top Layer w20: v3@3027,1443 v2(3027,1574.12) ; C11.1@3489.19,1721.17 C12.2@3535.19,1721.17 3559.38,1721.17 3583,1697.55 3723.38,1697.55 v1(3747,1721.17) ; C20.1@3513,2004.64 v1(3553.75,2004.64) J1.4@3610.05,2004.64 ; v1(3883,1721.17) 3910.53,1693.64 4023.43,1693.64 4033,1684.07 U3.2@4033,1640
  Top Layer w40: v2(3433,1727.37) C11.1@3470.61,1727.37
  Bottom Layer w8: v3(782.25,872.96) v3(893.5,873) 1089.09,873 v3(1120.41,841.68) ; v3(1407,873) 1612.95,873 v3(1651.82,834.13) ; v3(2479.07,886.83) 2664.4,886.83 v3(2710.11,841.12) ; v3(2776.04,2089.95) 2842.12,2156.03 2842.12,2233.65 2934.09,2325.62 v3(2966.23,2325.62)
  Bottom Layer w11: v3@2966.23,2324.74 3272.96,2324.74 v3(3274.26,2326.04) 3393.4,2326.04 3420.44,2353.07 v3(3498.11,2353.07) 3622.51,2353.07 3683,2292.58 v3(3683,2166.06)
  Bottom Layer w15: v3(1017.24,1203.24) 1136.52,1322.52 1875.48,1322.52 1894,1304 v3(1953.46,1304) 2123,1304 2156,1337 2410.75,1337 2445.75,1372 v3@2562,1372 ; v3(2562,1371) 2650.46,1371 2659.46,1380 2896.29,1380 2944.48,1428.19 2945.19,1428.19 2957.85,1440.85 v3(3027,1440.85) ; 2842.12,1377.6 2860.65,1359.08 v3@2873.38,1359.08 ; 2857.35,1377.72 2875.88,1359.2 2894.4,1377.72
  Bottom Layer w20: v1(3747,1721.17) v1(3883,1721.17)
  Bottom Layer w30: v2(3027,1574.12) 3191.85,1574.12 3215.15,1597.41 3388,1597.41 3433,1642.41 v2(3433,1727.37) 3470.61,1764.98 3470.61,1921.5 v1(3553.75,2004.64)
  other v3: 1461.07,1319.02
+5V: C4.1 C5.1 C6.1 C19.2 L1.2 P13.4 P15.1 P16.3 P17.4 P18.4 P20.3 R4.1 U2.3 U4.14 | length 2765.1
  Top Layer w8: C4.1@2409.94,1672.27 2409.94,1712.07 R4.1@2410.02,1712.15
  Top Layer w10: R4.1@2410.02,1712.15 2414.86,1717 2415.18,1717 2450.55,1752.37 2713.22,1752.37 2740.17,1725.41 2740.17,1711.27 2749.47,1701.97 L1.2@2763.61,1701.97 ; U4.14@2548.34,1847.38 C19.2@2607.84,1847.38 ; C19.2@2607.84,1847.97 2655.67,1847.97 2662.5,1841.13 ; 2895.73,1825.79 2897.45,1827.51
  Top Layer w15: P13.4@3212.38,1282.85 3260.36,1234.87 3260.36,1043.35 3310,993.71 3310,886.94 3359,837.94 3440.32,837.94 P15.1@3494,784.26
  Top Layer w30: P16.3@2463.68,2251 2522.31,2192.38 2522.31,2168.18 2635.63,2054.86 2635.63,2053.48 2687.26,2001.86 2812.19,2001.86 2845.14,1968.9 2917.46,1968.9 2935.04,1951.33 U2.3@2935.04,1898.48 ; L1.2@2767.61,1684.77 2848.32,1684.77 2864.82,1668.28 2864.82,1661.34 2931,1595.16 2931,1365.48 P17.4@3013.62,1282.85 ; 2898.68,1799.88 2909.46,1799.88 2939.56,1829.98 2939.56,1893.79 2935.04,1898.31 U2.3@2935.04,1898.48 ; U2.3@2939.72,1893.79 U2.3@2935.04,1898.48
  Bottom Layer w40: P17.4@3013.62,1282.85 P13.4@3212.38,1282.85
+24V: F1.1 F2.1 P14.1
+24VMOT: C2.2 C3.1 C8.2 C42.1 C44.1 C54.2 C55.2 C58.2 C59.2 C60.1 C61.1 C72.1 C74.1 C84.2 C85.2 C88.2 C89.2 C90.1 C91.1 D3.2 F1.2 P19.1 P19.3 P19.5 R1.2 U1.3 U6.22 U6.28 U7.22 U7.28 U8.22 U8.28 U9.22 U9.28 | length 6918.9
  Top Layer w8: R1.2@2318.96,1632.68 R1.2@2319.5,1632.13 R1.2@2320.05,1631.59
  Top Layer w15: v1(1239.78,807.94) C44.1@1274.44,807.94 ; C44.1@1273.44,805.94 C44.1@1275.83,808.34 ; v1(1774.11,807.94) C74.1@1808.77,807.94 ; C74.1@1807.77,805.94 C74.1@1810.17,808.34 ; v2@2286.39,1632.68 R1.2@2318.96,1632.68 ; v1(2308.45,807.94) C42.1@2343.1,807.94 ; C42.1@2342.1,805.94 C42.1@2344.5,808.34 ; v1(2842.78,807.94) C72.1@2877.44,807.94 ; C72.1@2876.44,805.94 C72.1@2878.83,808.34
  Top Layer w50: 633.55,1096.93 633.55,757.19 672.02,718.73 P19.3@672.02,449.44 P19.5@672.02,349.44
  Bottom Layer w50: v6(974.98,463.1) v6(1002.98,463.1) v6(1172.24,463.1) v6(1200.24,463.1) 1221.5,463.1 1297.86,539.46 1297.86,749.86 v1(1239.78,807.94) 1239.78,963.68 v2(1239.41,964.05) 1239.03,963.68 v2@1191.82,963.68 ; v2(1191.44,964.05) v2@1191.82,963.68 ; v2(1239.41,915.34) 1239.41,916.09 v2@1191.82,963.68 ; v6(1509.31,463.1) v6(1537.31,463.1) v6(1706.57,463.1) v6(1734.57,463.1) 1755.83,463.1 1832.19,539.46 1832.19,749.86 v1(1774.11,807.94) 1774.11,963.68 v2(1773.74,964.05) 1773.55,964.24 1725.96,964.24 v2(1725.78,964.05) 1773.74,916.09 v2(1773.74,915.34) ; v6(2043.64,463.1) v6(2071.64,463.1) v6(2240.9,463.1) v6(2268.9,463.1) 2287.43,463.1 2350.9,526.57 2350.9,765.49 v1(2308.45,807.94) 2308.45,963.68 v2(2308.07,964.05) v2(2260.11,964.05) 2308.07,916.09 v2(2308.07,915.34) ; v6(2577.98,463.1) v6(2605.98,463.1) v6(2775.24,463.1) v6(2803.24,463.1) 2824.5,463.1 2900.86,539.46 2900.86,749.86 v1(2842.78,807.94) 2842.78,963.68 v2(2842.41,964.05) 2842.22,964.24 2794.63,964.24 v2(2794.44,964.05) 2842.41,916.09 v2(2842.41,915.34)
  Bottom Layer w118.11: 813.09,1114.68 v2(1148.87,1114.68) v2(1196.83,1114.68) 1244.01,1114.68 v2(1244.8,1114.68) ; v2@1248.58,1114.68 v2(1780.89,1114.68) v2@2217.53,1114.68 ; v2(2220.74,1114.68) v2(2268.7,1114.68) v2(2316.66,1114.68) ; v2@2313.46,1114.68 v2@2755.07,1114.68 ; 2485.55,1114.68 v2(2851.58,1114.68)
  other v2: 1684.96,1114.68 1732.92,1114.68 2755.65,1114.68 2803.61,1114.68 660.3,1237.52 704.8,1237.52 749.31,1237.52 793.82,1237.52 639.5,1278.52 684.01,1278.52 728.51,1278.52 773.02,1278.52 2227.7,1620.55 2268.7,1641.35 2509.97,1660.77 2227.7,1665.06 2268.7,1685.86 2489.17,1701.77 2533.68,1701.77
D+: C25.2 J2.3 P15.4 R37.1 | length 574.7
  Top Layer w8: R37.1@3346.68,699.56 3389,699.56 3408.68,699.56 3426,682.25 3426,552.26 P15.4@3494,484.26 3563.74,484.26 3605,443 3668.09,443 J2.3@3718.21,493.13
D-: C23.2 J2.2 P15.3 R36.1 | length 437.8
  Top Layer w8: R36.1@3347.68,742.56 3389,742.56 3409,742.56 3444,707.56 3444,634.26 P15.3@3494,584.26 3548.08,584.26 J2.2@3639.21,493.13
DTR: R5.1 T2.2 U5.13 | length 593.6
  Top Layer w8: U5.13@3037.28,646.89 3091.85,646.89 3132.63,606.11 3132.63,514.18 3213.58,433.23 3227.9,433.23 R5.1@3230.73,430.39 v3(3230.73,459.63) ; T2.2@3364.46,421.35 3371.29,428.18 T2.2@3372.28,428.18 v3@3403.35,428.18
  Bottom Layer w8: v3(3230.73,459.63) 3371.9,459.63 v3(3403.37,428.15)
E0_DIR: U3.28 U8.19 | length 2275.7
  Top Layer w8: v3(2460.36,1256.5) 2460.1,1256.24 2458.01,1256.24 2435,1233.23 2435,726.09 2487.42,673.67 U8.19@2592.07,673.67 ; v3(3529.25,1293.75) 3529.26,1034.08 3583,980.34 U3.28@3583,912
  Bottom Layer w8: v3(2460.36,1256.5) 2460.36,1258.59 2485.27,1283.5 2515.15,1283.5 2526.9,1271.75 2887.63,1271.75 2976.57,1360.69 3260.17,1360.69 3306.85,1314.01 3509.01,1314.01 v3@3529.25,1293.77
E0_STEP: U3.27 U8.16 | length 2102.7
  Top Layer w8: v3(2494,1257) 2494,1255.49 2451,1212.49 2451,783.72 2502.01,732.71 U8.16@2592.07,732.73 ; v3(3504,1271.85) 3504,1019.84 3533,990.84 U3.27@3533,912
  Bottom Layer w8: v3(2494,1257) 2495.25,1255.75 2894.26,1255.75 2983.2,1344.69 3253.54,1344.69 3304.9,1293.33 3482.52,1293.33 v3(3504,1271.85)
EN: C13.1 R15.1 R21.2 T1.3 U3.3 | length 2737
  Top Layer w8: v3@3317.54,615.06 T1.3@3346.68,615.06 ; R21.2@3455.75,2282.37 R15.1@3498.11,2282.37 3536.76,2282.37 C13.1@3537.11,2282.02 3559.14,2282.02 3590.47,2250.69 3723.48,2250.69 3861.56,2112.6 v3(3861.56,1806.51) ; U3.3@3983,1640 v3(3983,1589.35) 3983,1520.92 4060,1443.92 v3@4060,1128.58
  Bottom Layer w8: v3(3314.83,615.34) 3314.83,886.83 3366,938 3874.1,938 v3(4060,1123.9) ; v3(3861.56,1806.51) 3983,1685.07 v3(3983,1589.35)
FAN_E0: R32.1 U3.16 U4.9 | length 1898.9
  Top Layer w8: R32.1@2351.83,1808.99 2351.88,1809.05 U4.9@2441.06,1808.99 U4.9@2441.06,1808.99 ; R32.1@2351.83,1809.05 v3(2351.83,1841.04) ; U3.16@3364,1450 3354.88,1459.12 3325.78,1459.12 3317.51,1467.39 3317.51,1505.79 3306.26,1517.05 3306.26,1773.18 v3(3378,1844.93)
  Bottom Layer w8: v3(2351.83,1841.04) 2433.15,1922.36 2433.83,1922.36 2465.83,1954.36 2505.26,1954.36 2524.58,1973.68 2774.41,1973.68 2877.73,2077 3235,2077 3251,2061 3319,2061 3378,2002 v3(3378,1844.93)
FAN_E0_5V: R10.2 R11.1 U4.8 | length 244.7
  Top Layer w8: R11.1@2338.18,1963.48 R10.2@2292.82,1963.48 2292.82,1909.62 2327.94,1874.5 2359.73,1874.5 2386.85,1847.38 U4.8@2412.52,1847.38
FAN_VCC: D2.2 P2.2 P16.2 | length 397.3
  Top Layer w8: P16.2@2363.68,2251 2363.68,2203 2383.92,2182.76 2436.92,2182.76 2460.76,2158.93 D2.2@2460.76,2157.93
  Top Layer w20: P2.2@2298.68,2457 2363.68,2392 P16.2@2363.68,2251
GND: C2.1 C3.2 C5.2 C6.2 C7.1 C8.1 C9.1 C10.1 C11.2 C12.1 C13.2 C14.2 C15.2 C16.1 C17.2 C18.2 C19.1 C20.2 C21.1 C22.1 C23.1 C24.2 C25.1 C32.1 C34.2 C36.2 C38.1 C40.1 C54.1 C55.1 C58.1 C59.1 C60.2 C61.2 C84.1 C85.1 C88.1 C89.1 C90.2 C91.2 D3.1 D4.1 EXT-RST.2 J1.6 J1.10 J1.11 J1.12 J1.13 J2.4 L7.2 P1.2 P3.2 P5.2 P6.2 P12.3 P13.3 P14.2 P15.5 P17.3 P18.3 P19.2 P19.4 P19.6 Q1.2 Q2.1 Q2.2 Q2.3 Q3.1 Q3.2 Q3.3 R8.1 R9.2 R11.2 R20.2 R22.1 R28.2 R30.2 R31.2 R32.2 R65.1 R66.1 R67.1 R68.1 R73.1 R74.1 R75.1 R76.1 SW1.2 U1.1 U2.1 U3.1 U3.15 U3.38 U4.1 U4.4 U4.7 U4.10 U4.13 U4.15 U5.1 U6.3 U6.9 U6.10 U6.13 U6.18 U6.25 U6.EXPAD U7.3 U7.10 U7.13 U7.18 U7.25 U7.EXPAD U8.3 U8.9 U8.13 U8.18 U8.25 U8.EXPAD U9.3 U9.13 U9.18 U9.25 U9.EXPAD U10.3 | length 2629.2
  Top Layer w8: U7.13@1048.24,791.89 1048.24,824.52 v3@1054.41,830.68 ; C24.2@1095.61,878.59 1095.61,829.48 1107.29,817.8 ; U7.10@1107.29,791.89 1107.29,817.8 ; 1107.41,817.68 1107.29,817.8 ; U7.3@1186.14,673.67 1250.32,673.67 1262.58,661.41 1292.21,661.41 1299.24,668.44 1299.24,677.42 1303.5,681.68 ; Q1.2@2367.63,2061.86 2367.63,2060.55 Q1.2@2383.31,2044.87 ; v2(2480.43,1876.91) U4.4@2480.43,1944.82 ; C21.1@3346.68,658.21 3388.71,658.21 C25.1@3389,657.92 3399.74,647.17 3399.74,631.73 v3(3401.35,630.12) ; R22.1@3391.21,1733.53 3394.68,1737 3394.68,1750.68 3412,1768 3476.28,1768 3483,1774.72 C11.2@3483,1802.17 3524,1802.17 3535.19,1790.98 C12.1@3535.19,1760.54 ; v3@3553.75,1921.22 v3(3556.95,1918.02) J1.6@3610.05,1918.02
  Top Layer w10: U7.25@1087.61,594.82 v4(1087.61,646.05) ; v3(1475.97,703.89) 1486.5,693.36 U9.18@1523.41,693.36 v4(1621.94,693.36) ; U9.13@1582.57,791.89 1582.57,732.73 v4(1621.94,693.36) ; U9.25@1621.94,594.82 v4(1621.94,646.05) v4(1621.94,693.36) ; U9.EXPAD@1661.31,732.73 v4(1621.94,693.36) ; U9.3@1720.48,673.67 1641.63,673.67 v4(1621.94,693.36) ; v3(2007.24,703.89) 2010.07,703.89 2020.6,693.36 U6.18@2057.74,693.36 v4(2156.27,693.36) ; U6.13@2116.9,791.89 2116.9,732.73 v4(2156.27,693.36) ; U6.25@2156.27,594.82 v4(2156.27,646.05) v4(2156.27,693.36) ; U6.10@2175.96,791.89 U6.EXPAD@2175.96,713.04 ; U6.9@2195.64,791.89 2195.64,732.73 U6.EXPAD@2175.96,713.04 ; U6.3@2254.81,673.67 2175.96,673.67 v4(2156.27,693.36) ; v3@2544.4,703.89 2554.94,693.36 U8.18@2592.07,693.36 v4(2690.61,693.36) ; U8.13@2651.24,791.89 2651.24,732.73 v4(2690.61,693.36) ; U8.25@2690.61,594.82 v4(2690.61,693.36) ; U8.9@2729.98,791.89 2729.98,732.73 v4(2690.61,693.36) ; U8.3@2789.14,673.67 2710.29,673.67 v4(2690.61,693.36) ; v4(2156.27,693.36) U6.EXPAD@2175.96,713.04
  Top Layer w19.68: v3(2319.45,1752.68) 2319.77,1752.37 2319.77,1712.33 R9.2@2320.08,1712.33
  Top Layer w30: Q1.2@2383.31,2049.87 v2@2416.69,2049.87
  other v1: 1332.24,110.41 1932.24,110.41 2382.24,110.41 2982.24,110.41 3132.24,110.41 3282.24,110.41 3432.24,110.41 3582.24,110.41 3732.24,110.41 1857.24,260.41 3207.24,260.41 3657.24,260.41 3957.24,260.41 1336.22,324.47 1762.96,330.03 2294.79,330.03 2831.46,330.98 1227.12,336.03 1481.34,335.98 2549.38,335.98 947.97,337.97 2016.02,338.98 1336.22,360.41 1762.96,365.98 2294.79,365.98 2831.46,366.92 1227.12,371.97 1481.34,371.92 2549.38,371.92 947.97,373.92 2016.02,374.92 1336.22,396.36 1762.96,401.92 2294.79,401.92 2831.46,405.1 1481.34,407.87 2549.38,407.87 1227.12,407.92 947.97,409.87 2016.02,410.87 2982.24,410.41 3582.24,410.41 3732.24,410.41 3882.24,410.41 4032.24,410.41 1336.22,432.3 1226.53,546.78 2296.12,546.77 948.98,548.33 1483.32,548.33 1760.65,548.33 2017.65,548.33 2551.98,548.33 2828.49,548.33 3957.24,560.41 1201.37,577.08 2270.96,577.07 974.15,578.63 1508.48,578.63 1735.49,578.63 2042.82,578.63 2577.15,578.63 2803.32,578.64 3132.24,710.41 3582.24,710.41 3732.24,710.41 3882.24,710.41 4032.24,710.41 1857.24,860.41 2007.24,860.41 1445.5,944.75 1481.44,944.75 2563.92,952.6 2599.86,952.6 1301.41,973.68 945.35,980.69 981.3,980.69 1017.24,980.69 1445.5,980.69 1481.44,980.69 1981.27,980.69 2017.22,980.69 2053.17,980.69 2089.11,980.69 2563.92,988.54 2599.86,988.54 957.24,1460.41 1107.24,1460.41 1257.24,1460.41 1407.24,1460.41 1557.24,1460.41 1707.24,1460.41 1857.24,1460.41 2007.24,1460.41 2157.24,1460.41 2307.24,1460.41 1632.24,1610.41 1707.24,1760.41 3732.24,1910.41 4032.24,1910.41 3957.24,2060.41 3882.24,2210.41 4032.24,2210.41 2457.24,2360.41 2757.24,2360.41 2907.24,2360.41 3057.24,2360.41 3357.24,2360.41 3807.24,2360.41 882.24,2510.41 1182.24,2510.41 2382.24,2510.41 2532.24,2510.41 2682.24,2510.41 2832.24,2510.41 2982.24,2510.41 3132.24,2510.41 3282.24,2510.41
  other v2: 1699.66,1594.44 1754.16,1594.44 1808.67,1594.44 1863.18,1594.44 1917.68,1594.44 1972.19,1594.44 2027.69,1594.44 2083.2,1594.44 1289.56,1595.43 1344.07,1595.43 1398.58,1595.43 1453.08,1595.43 1508.59,1595.43 1564.1,1595.43 1666.58,1643.87 1721.09,1643.87 1775.59,1643.87 1830.1,1643.87 1884.61,1643.87 1939.11,1643.87 1993.62,1643.87 2049.12,1643.87 2104.63,1643.87 1256.49,1644.86 1310.99,1644.86 1365.5,1644.86 1420.01,1644.86 1474.51,1644.86 1530.02,1644.86 1585.53,1644.86 1700.29,1692.87 1754.79,1692.87 1809.3,1692.87 1863.81,1692.87 1918.31,1692.87 1972.82,1692.87 2028.33,1692.87 2083.83,1692.87 1290.2,1693.86 1344.7,1693.86 1399.21,1693.86 1453.72,1693.86 1509.22,1693.86 1564.73,1693.86 1257.12,1743.28 1311.63,1743.28 1366.13,1743.28 2413.69,2049.87 889.44,2458.57 995.06,2457.94 1093.49,2458.57 1191.92,2457.94 1044.06,2491.65 1142.92,2491.65 938.44,2492.28
  other v3: 2953.48,236.39 2953.48,271.9 1890.71,405.14 1890.71,441.08 1890.71,477.03 1915.74,506.89 1915.74,542.84 1380.34,557.11 1915.74,578.78 1380.34,593.05 1915.74,614.73 1380.34,629 1380.34,664.94 2541.58,703.89 934.4,704.78 1053.41,830.68 2185.74,834.68 1296.1,853.44
  other v4: 1040.3,646.05 1134.92,646.05 1574.63,646.05 1669.25,646.05 2108.97,646.05 2203.58,646.05 2643.3,646.05 2690.61,646.05 2737.92,646.05 1040.3,693.36 1087.61,693.36 1134.92,693.36 1574.63,693.36 1669.25,693.36 2108.97,693.36 2203.58,693.36 2643.3,693.36 2737.92,693.36 1040.3,740.67 1087.61,740.67 1134.92,740.67 1574.63,740.67 1621.94,740.67 1669.25,740.67 2108.97,740.67 2156.27,740.67 2203.58,740.67 2643.3,740.67 2690.61,740.67 2737.92,740.67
